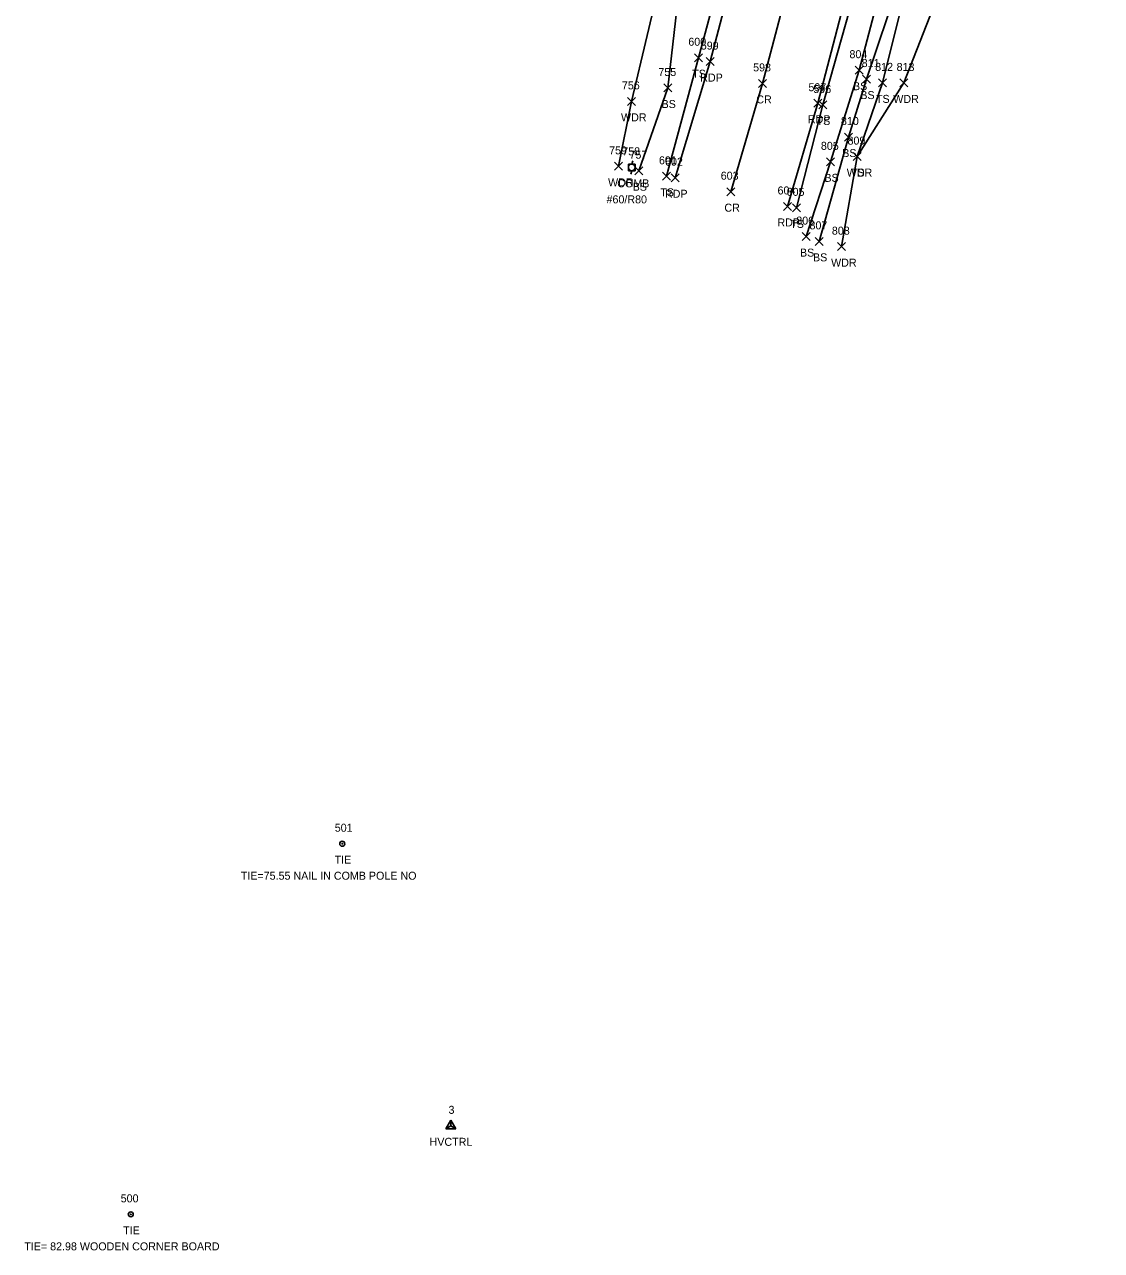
# Model space of a CAD drawing. Extents: x 1638705 to 1644019, y 630225 to 637423.
# Drawn here: x 1643662.2 to 1643931.4, y 636595.3 to 636901.8 of the extents above; entities that cross this region are included whole.
import ezdxf

# ---------------------------------------------------------------- set-up
doc = ezdxf.new("R2010")
doc.units = 0
for name, color, linetype in [('C_A', 7, 'Continuous'), ('C_C', 7, 'Continuous'), ('C_I', 7, 'Continuous'), ('CBP', 7, 'Continuous'), ('CPSM', 7, 'Continuous'), ('L_A', 7, 'Continuous'), ('L_I', 7, 'Continuous'), ('L_TIC', 7, 'Continuous'), ('LAWA', 7, 'Continuous'), ('LELB', 7, 'Continuous'), ('P_A', 7, 'Continuous'), ('P_I', 7, 'Continuous'), ('P_TIC', 7, 'Continuous'), ('PET', 7, 'Continuous'), ('PRC', 7, 'Continuous'), ('U_A', 7, 'Continuous'), ('U_C', 7, 'Continuous'), ('U_I', 7, 'Continuous'), ('UP', 7, 'Continuous')]:
    doc.layers.add(name, color=color, linetype=linetype)

msp = doc.modelspace()

# ---------------------------------------------------------------- linework, layer by layer
at = {"layer": 'CBP'}
for centre, radius in [((1643741.59, 636696.98), 0.625), ((1643741.59, 636696.98), 0.0833), ((1643688.73, 636604.33), 0.625), ((1643688.73, 636604.33), 0.0833)]:
    msp.add_circle(centre, radius, dxfattribs=at)
at = {"layer": 'CPSM'}
for p, q in [((1643767.46, 636625.74), (1643768.71, 636627.91)), ((1643769.96, 636625.74), (1643768.71, 636627.91)), ((1643768.71, 636626.46), (1643768.71, 636627.91)), ((1643767.46, 636625.74), (1643768.71, 636626.46)), ((1643767.46, 636625.74), (1643769.96, 636625.74)), ((1643768.71, 636626.46), (1643768.71, 636626.46)), ((1643768.71, 636626.46), (1643769.96, 636625.74))]:
    msp.add_line(p, q, dxfattribs=at)
at = {"layer": 'L_TIC'}
for points in [[(1643829.67, 636892.45), (1643831.67, 636894.45)], [(1643831.67, 636892.45), (1643829.67, 636894.45)], [(1643869.82, 636889.34), (1643871.82, 636891.34)], [(1643871.82, 636889.34), (1643869.82, 636891.34)], [(1643871.66, 636887.12), (1643873.66, 636889.12)], [(1643873.66, 636887.12), (1643871.66, 636889.12)], [(1643875.6, 636886.17), (1643877.6, 636888.17)], [(1643877.6, 636886.17), (1643875.6, 636888.17)], [(1643880.97, 636886.15), (1643882.97, 636888.15)], [(1643882.97, 636886.15), (1643880.97, 636888.15)], [(1643821.97, 636884.89), (1643823.97, 636886.89)], [(1643823.97, 636884.89), (1643821.97, 636886.89)], [(1643812.91, 636881.55), (1643814.91, 636883.55)], [(1643814.91, 636881.55), (1643812.91, 636883.55)], [(1643860.76, 636880.64), (1643862.76, 636882.64)], [(1643862.76, 636880.64), (1643860.76, 636882.64)], [(1643867.13, 636872.63), (1643869.13, 636874.63)], [(1643869.13, 636872.63), (1643867.13, 636874.63)], [(1643869.33, 636867.74), (1643871.33, 636869.74)], [(1643871.33, 636867.74), (1643869.33, 636869.74)], [(1643869.33, 636867.74), (1643871.33, 636869.74)], [(1643871.33, 636867.74), (1643869.33, 636869.74)], [(1643809.67, 636865.31), (1643811.67, 636867.31)], [(1643811.67, 636865.31), (1643809.67, 636867.31)], [(1643814.74, 636864.22), (1643816.74, 636866.22)], [(1643816.74, 636864.22), (1643814.74, 636866.22)], [(1643862.68, 636866.43), (1643864.68, 636868.43)], [(1643864.68, 636866.43), (1643862.68, 636868.43)], [(1643821.68, 636862.82), (1643823.68, 636864.82)], [(1643823.68, 636862.82), (1643821.68, 636864.82)], [(1643854.17, 636854.93), (1643856.17, 636856.93)], [(1643856.17, 636854.93), (1643854.17, 636856.93)], [(1643856.57, 636847.74), (1643858.57, 636849.74)], [(1643858.57, 636847.74), (1643856.57, 636849.74)], [(1643859.83, 636846.55), (1643861.83, 636848.55)], [(1643861.83, 636846.55), (1643859.83, 636848.55)], [(1643865.42, 636845.23), (1643867.42, 636847.23)], [(1643867.42, 636845.23), (1643865.42, 636847.23)]]:
    msp.add_lwpolyline(points, dxfattribs=at)
at = {"layer": 'LAWA'}
for points in [[(1643865.64, 637303.77), (1643862.82, 637270.27), (1643861.25, 637253.7), (1643870.99, 637241.9), (1643867.11, 637203.42), (1643864.21, 637161.34), (1643862.97, 637130.77), (1643854.22, 637098.04), (1643864.2, 637092.72), (1643858.24, 637074.74), (1643852.38, 637053.09), (1643849.03, 637029.11), (1643850.77, 637013.92), (1643837.37, 636980.48), (1643832.85, 636980.73), (1643828.82, 636965.18), (1643821.8, 636940.41), (1643821.76, 636915.63), (1643813.91, 636882.55), (1643810.67, 636866.31)], [(1643866.42, 636846.23), (1643870.33, 636868.74), (1643881.97, 636887.15), (1643890.89, 636910.04), (1643901.92, 636941.2), (1643899.23, 636950.31), (1643899.4, 636965.43), (1643906.72, 636979.6), (1643908.72, 636993.2), (1643928.1, 637008.65), (1643931.38, 637033.38), (1643927.97, 637042.71)]]:
    msp.add_lwpolyline(points, dxfattribs=at)
at = {"layer": 'LELB'}
for points in [[(1643917.29, 637304.48), (1643919.24, 637262.47), (1643916.89, 637218.55), (1643914.08, 637180.95), (1643910.3, 637135.87), (1643913.16, 637114.46), (1643911.21, 637098.67), (1643904.37, 637090.61), (1643898.51, 637049.58), (1643891.41, 637000.85), (1643892.59, 636975.41), (1643882.01, 636960.09), (1643871.05, 636914.88), (1643861.76, 636881.64), (1643855.17, 636855.93)], [(1643881.31, 637303.51), (1643880.47, 637260.36), (1643877.75, 637219.48), (1643872.16, 637183.49), (1643871.11, 637167.53), (1643875.06, 637139.18), (1643871.64, 637093.85), (1643865.67, 637053.39), (1643855.97, 637011.76), (1643842.4, 636975.8), (1643838.3, 636921.94), (1643830.67, 636893.45), (1643822.68, 636863.82)], [(1643828.82, 636965.18), (1643828.51, 636937.87), (1643825.85, 636910.8), (1643822.97, 636885.89), (1643815.74, 636865.22)], [(1643860.83, 636847.55), (1643868.13, 636873.63), (1643872.66, 636888.12), (1643880.75, 636912.17), (1643892.11, 636934.85), (1643890.24, 636948.66), (1643888.1, 636950.47), (1643889.82, 636959.7), (1643892.86, 636964.57), (1643894.09, 636964.51), (1643891.57, 636957.99), (1643889.88, 636951.78)], [(1643870.33, 636868.74), (1643876.6, 636887.17), (1643883.1, 636913.38), (1643894.64, 636933.18), (1643894.56, 636950.41), (1643899.4, 636965.43)], [(1643884.56, 636948.28), (1643881.76, 636932.79), (1643876.88, 636913.48), (1643870.82, 636890.34), (1643863.68, 636867.43), (1643857.57, 636848.74)]]:
    msp.add_lwpolyline(points, dxfattribs=at)
at = {"layer": 'P_TIC'}
for points in [[(1643832.58, 636891.49), (1643834.58, 636893.49)], [(1643834.58, 636891.49), (1643832.58, 636893.49)], [(1643845.66, 636886.04), (1643847.66, 636888.04)], [(1643847.66, 636886.04), (1643845.66, 636888.04)], [(1643859.5, 636881.08), (1643861.5, 636883.08)], [(1643861.5, 636881.08), (1643859.5, 636883.08)], [(1643823.77, 636862.46), (1643825.77, 636864.46)], [(1643825.77, 636862.46), (1643823.77, 636864.46)], [(1643837.69, 636858.97), (1643839.69, 636860.97)], [(1643839.69, 636858.97), (1643837.69, 636860.97)], [(1643851.88, 636855.28), (1643853.88, 636857.28)], [(1643853.88, 636855.28), (1643851.88, 636857.28)]]:
    msp.add_lwpolyline(points, dxfattribs=at)
at = {"layer": 'PET'}
for points in [[(1643915.42, 637304.49), (1643914.6, 637262.42), (1643913.48, 637219.01), (1643911.31, 637181.13), (1643907.88, 637136.04), (1643902.19, 637091.19), (1643896.2, 637050.09), (1643887.54, 637001.12), (1643879.88, 636960.46), (1643869.1, 636915.33), (1643860.5, 636882.08), (1643852.88, 636856.28)], [(1643886.09, 637303.33), (1643885.33, 637260.95), (1643884.29, 637219.34), (1643882.65, 637181.95), (1643878.66, 637138.56), (1643873.79, 637093.66), (1643868.41, 637053.44), (1643859.66, 637004.66), (1643851.59, 636964.82), (1643841.08, 636921.12), (1643833.58, 636892.49), (1643824.77, 636863.46)]]:
    msp.add_lwpolyline(points, dxfattribs=at)
at = {"layer": 'PRC'}
msp.add_lwpolyline([(1643901.07, 637302.92), (1643900.04, 637261.19), (1643898.85, 637218.55), (1643896.7, 637181.82), (1643893.13, 637137.2), (1643887.51, 637091.29), (1643882.08, 637051.36), (1643873.69, 637003.61), (1643865.54, 636962.88), (1643854.81, 636918.08), (1643846.66, 636887.04), (1643838.69, 636859.97)], dxfattribs=at)
at = {"layer": 'UP'}
for p, q in [((1643813.11, 636865.22), (1643813.11, 636866.88)), ((1643813.11, 636866.88), (1643814.77, 636866.88)), ((1643814.19, 636867.72), (1643813.94, 636866.88)), ((1643813.94, 636866.05), (1643813.94, 636866.05)), ((1643814.77, 636866.88), (1643814.77, 636865.22)), ((1643814.77, 636865.22), (1643813.11, 636865.22)), ((1643813.69, 636864.38), (1643813.94, 636865.22))]:
    msp.add_line(p, q, dxfattribs=at)
msp.add_circle((1643813.94, 636866.05), 0.833, dxfattribs=at)

# ---------------------------------------------------------------- texts
at = {"layer": 'C_A'}
for s, p in [('TIE', (1643739.67, 636691.98)), ('HVCTRL', (1643763.41, 636621.46)), ('TIE', (1643686.81, 636599.33))]:
    msp.add_text(s, height=2, dxfattribs=at).set_placement(p)
at = {"layer": 'C_C'}
for s, p in [('TIE=75.55 NAIL IN COMB POLE NO', (1643716.22, 636687.98)), ('TIE= 82.98 WOODEN CORNER BOARD', (1643662.09, 636595.33))]:
    msp.add_text(s, height=2, dxfattribs=at).set_placement(p)
at = {"layer": 'C_I'}
for s, p in [('501', (1643739.71, 636699.98)), ('3', (1643768.15, 636629.46)), ('500', (1643686.2, 636607.33))]:
    msp.add_text(s, height=2, dxfattribs=at).set_placement(p)
at = {"layer": 'L_A'}
for s, p in [('TS', (1643829.08, 636888.45)), ('BS', (1643869.26, 636885.34)), ('BS', (1643871.1, 636883.12)), ('TS', (1643875.01, 636882.17)), ('WDR', (1643879.33, 636882.15)), ('BS', (1643821.41, 636880.89)), ('WDR', (1643811.27, 636877.55)), ('TS', (1643860.17, 636876.64)), ('BS', (1643866.57, 636868.63)), ('TS', (1643868.74, 636863.74)), ('WDR', (1643808.03, 636861.31)), ('BS', (1643862.12, 636862.43)), ('WDR', (1643867.7, 636863.74)), ('BS', (1643814.18, 636860.22)), ('TS', (1643821.09, 636858.82)), ('TS', (1643853.58, 636850.93)), ('BS', (1643856.01, 636843.74)), ('BS', (1643859.27, 636842.55)), ('WDR', (1643863.79, 636841.23))]:
    msp.add_text(s, height=2, dxfattribs=at).set_placement(p)
at = {"layer": 'L_I'}
for s, p in [('600', (1643828.1, 636896.45)), ('804', (1643868.38, 636893.34)), ('755', (1643820.61, 636888.89)), ('811', (1643871.43, 636891.12)), ('812', (1643874.81, 636890.17)), ('813', (1643880.17, 636890.15)), ('756', (1643811.49, 636885.55)), ('596', (1643859.35, 636884.64)), ('810', (1643866.25, 636876.63)), ('805', (1643861.24, 636870.43)), ('809', (1643867.89, 636871.74)), ('809', (1643867.89, 636871.74)), ('759', (1643808.3, 636869.31)), ('757', (1643813.38, 636868.22)), ('601', (1643820.76, 636866.82)), ('605', (1643852.68, 636858.93)), ('806', (1643855.08, 636851.74)), ('807', (1643858.39, 636850.55)), ('808', (1643863.98, 636849.23))]:
    msp.add_text(s, height=2, dxfattribs=at).set_placement(p)
at = {"layer": 'P_A'}
for s, p in [('RDP', (1643831.07, 636887.49)), ('CR', (1643845.09, 636882.04)), ('RDP', (1643857.98, 636877.08)), ('RDP', (1643822.26, 636858.46)), ('CR', (1643837.12, 636854.97)), ('RDP', (1643850.37, 636851.28))]:
    msp.add_text(s, height=2, dxfattribs=at).set_placement(p)
at = {"layer": 'P_I'}
for s, p in [('599', (1643831.21, 636895.49)), ('598', (1643844.3, 636890.04)), ('597', (1643858.13, 636885.08)), ('602', (1643822.28, 636866.46)), ('603', (1643836.2, 636862.97)), ('604', (1643850.4, 636859.28))]:
    msp.add_text(s, height=2, dxfattribs=at).set_placement(p)
at = {"layer": 'U_A'}
msp.add_text('COMB', height=2, dxfattribs=at).set_placement((1643810.33, 636861.05))
at = {"layer": 'U_C'}
msp.add_text('#60/R80', height=2, dxfattribs=at).set_placement((1643807.65, 636857.05))
at = {"layer": 'U_I'}
msp.add_text('758', height=2, dxfattribs=at).set_placement((1643811.58, 636869.05))

doc.saveas('drawing.dxf')
